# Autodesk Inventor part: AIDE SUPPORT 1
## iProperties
Created: 2004-11
Part Number: AIDE SUPPORT 1
Document SubType Name: Modeling
Designer: Bruno
Manufacturer: Standard
Standards Organization: Custom
Author: Bruno
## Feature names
1. Base1
